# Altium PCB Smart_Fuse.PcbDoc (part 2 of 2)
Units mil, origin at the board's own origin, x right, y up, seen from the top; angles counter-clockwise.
Board outline 4000 x 2763 mil, 4 copper layers (Top Layer, Signal Layer 1, Signal Layer 2, Bottom Layer), stack 61.6 mil thick; 113 components, 65 nets, 281 pads, 450 vias.
Unrouted connection lines stored in the file: 2.
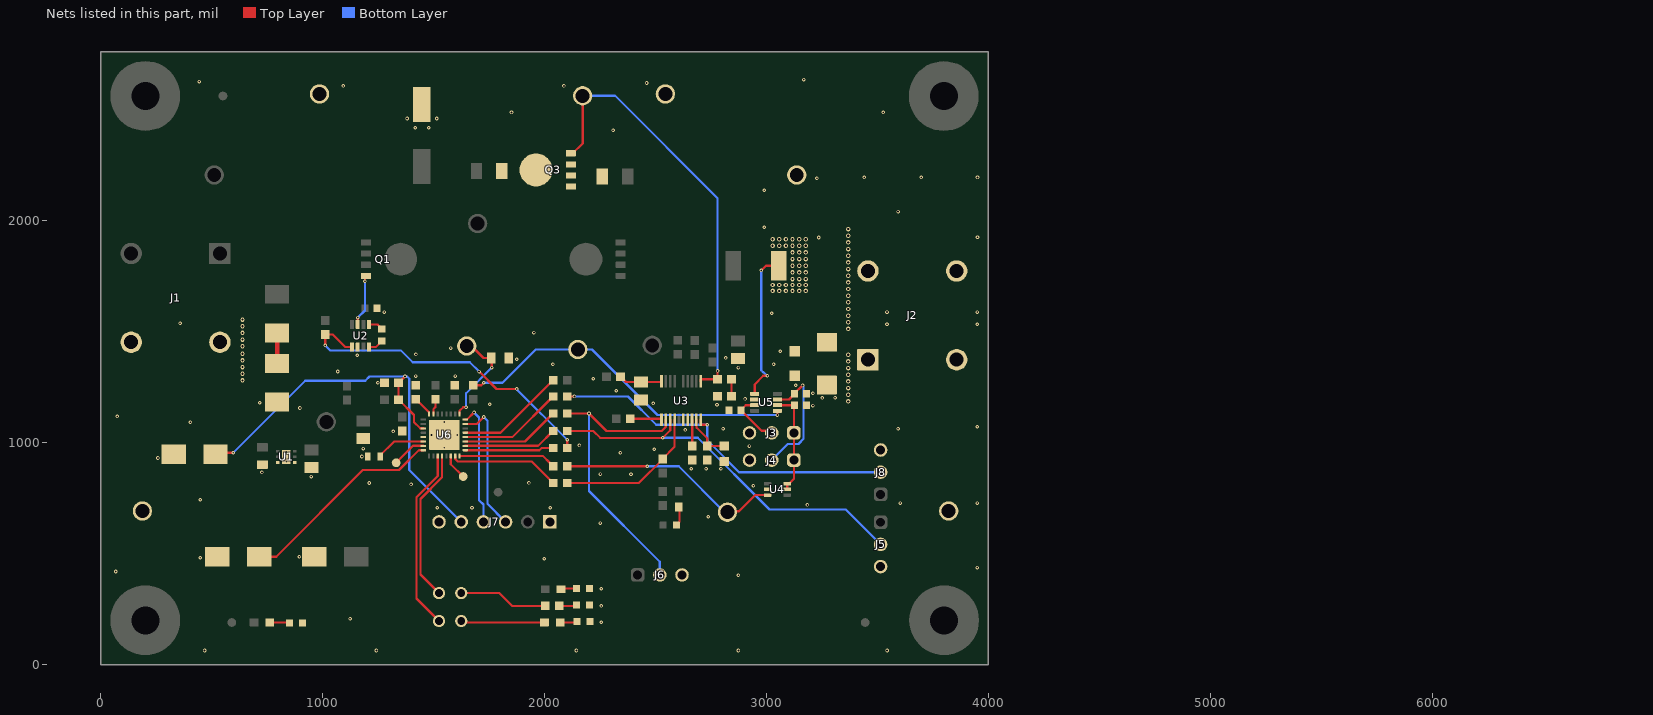
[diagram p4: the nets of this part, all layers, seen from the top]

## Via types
v1: diameter 20, hole 10, Top Layer to Bottom Layer, 262 vias
v2: diameter 16, hole 8, Top Layer to Bottom Layer, tented both sides, 179 vias
v3: diameter 19.68, hole 7.87, Top Layer to Bottom Layer, 7 vias
v4: diameter 34, hole 16, Top Layer to Bottom Layer, tented both sides, 2 vias

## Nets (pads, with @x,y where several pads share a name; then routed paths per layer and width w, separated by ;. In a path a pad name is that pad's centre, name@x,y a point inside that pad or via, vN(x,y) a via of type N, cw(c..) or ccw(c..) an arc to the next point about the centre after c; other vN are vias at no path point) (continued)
"Gate 2": Q3.4 R9.2 TP5.1 U3.11 | length 1994.7
  Top Layer w10: Q3.4@2118.01,2304.8 2126.87,2304.8 2171.12,2349.05 TP5.1@2171.12,2563.82 TP5.1@2171.12,2572.89 ; U3.11@2703.54,1277.07 2703.54,1285.37 2704.45,1286.28 R9.2@2779.16,1286.28 v2(2779.16,1323.83)
  Bottom Layer w10: TP5.1@2171.12,2563.82 2317.45,2563.82 2779.16,2102.11 v2(2779.16,1323.83)
GND: C1.1 C2.2 C3.2 C4.2 C5.2 C8.2 C9.2 C10.1 C11.2 C12.2 C13.2 C14.1 C15.1 C16.2 C17.2 C18.2 C19.1 D2.1 D3.2 D4.1 D6.2 D7.2 D8.2 D9.2 J1.2 J2.1 J3.3 J4.3 J5.3 J6.3 J7.1 J7.6 J8.3 R8.1 R10.2 R16.1 S1.1 S2.1 S3.1 TP9.1 TP10.1 TP11.1 TP12.1 U1.3 U1.4 U1.7@835.26,936.53 U2.2 U3.6 U3.7 U4.2 U5.2 U6.5 U6.33 | length 0.7
  Top Layer w10: U2.2@1157.34,1431.21 U2.2@1157.83,1430.72
  other v1: 3368,1186.73 3368,1216.73 3368,1246.73 3368,1276.73 637.98,1281.22 3368,1306.73 637.98,1311.22 3368,1336.73 637.98,1341.22 3368,1366.73 637.98,1371.22 3368,1396.73 637.98,1401.22 637.98,1435.31 637.98,1465.31 637.98,1495.31 637.98,1525.31 637.98,1555.31
  other v2: 467,64 1241.76,64 2143,64 2873,64 3543.31,64 2254.83,191.12 1122.76,207.16 2254.83,264.97 2254.83,341.99 2873,403 67,420 3950,437.57 1997.57,477.36 448,482 894.57,486.59 2250,638 2737,667 1516.16,707.59 1672.49,707.59 2025.51,707.59 3184.33,719.9 3602.36,728.35 3950,728.35 448,743.61 2940.61,806.54 1397.63,812.42 1209.38,818.83 1929.06,819 948.17,847.91 2389,858 2251,859 725.37,866.55 2660.5,883.24 2727.5,883.24 2794.5,883.24 257.01,931.56 1176.5,938.21 2341.57,955.59 2494,971 1182.26,973.72 2922.93,985 2156.46,988.33 1317.81,1051.07 2634,1058 2803.95,1062.99 3592.52,1062.99 3950,1071.92 403.54,1092.52 74,1119 896.82,1156.89 3208.8,1167.47 2776.66,1171.17 1752.81,1173.44 2488.81,1177.44 715.42,1180.52 2902.91,1197.5 3250.59,1202.13 3308.92,1202.67 3208.8,1222.9 2322.83,1234.17 3131.18,1259.63 1248.26,1270.56 2219.11,1288.56 1418.5,1300.48 1596.79,1300.48 1067.44,1321.36 2873,1339.09 2037.32,1354.09 3031.5,1354.35 1873.8,1376.73 2815.99,1382.53 1155.35,1394.56 1419.76,1398.52 1577.02,1426.93 1951.42,1496.8 3542.85,1533.76 3950,1533.76 357,1539 1276.59,1589.24 2308.34,2408.62 1416.7,2420.05 1477,2420.05 1380,2461.46 1513.7,2461.46 1850.39,2489.02 3526.16,2489.02 1092.52,2608.27 2086.61,2608.27 2459,2621.62 442.91,2627.95 3168,2637
  other v3: 835.26,914.88 835.26,958.19 1547.5,977.4 1489.43,1035.47 1547.5,1035.47 1605.57,1035.47 1547.5,1093.54
GPIO_EXTRA1: TP13.1 U6.7 | length 154.3
  Top Layer w10: TP13.1@1330.35,909.89 1406.71,986.25 U6.7@1453.01,986.25
GPIO_EXTRA2: TP14.1 U6.14 | length 115.9
  Top Layer w10: U6.14@1577.02,940.98 1577.02,903.43 TP14.1@1632.47,847.99
GPIO_FLT: R23.2 U6.21 | length 494.2
  Top Layer w10: U6.21@1641.99,1045.31 1801.1,1045.31 2037.32,1281.53 R23.2@2038.31,1281.53
GPIO_Ideal_Diode_EN: R19.2 U6.17 | length 400.7
  Top Layer w10: U6.17@1641.99,966.57 1975.99,966.57 1986.16,976.74 R19.2@2038.5,976.74
GPIO_INA_EN: R18.1 TP6.1 U4.3 | length 1058.6
  Top Layer w10: R18.1@2091.46,893.8 v2(2461.91,893.8) ; TP6.1@2823.5,687.29 2827.95,691.74 2876.14,691.74 2948.94,764.54 U4.3@3004.39,764.54
  Bottom Layer w10: v2(2461.91,893.8) 2603.8,893.8 2810.31,687.29 TP6.1@2851.62,687.29
GPIO_INA_EN_PIN: R18.2 U6.16 | length 442.2
  Top Layer w10: U6.16@1616.39,940.98 1991.33,940.98 2023.82,908.49 2023.82,907.51 2037.52,893.81 R18.2@2038.5,893.81
GPIO_INP: J5.2 R20.1 U3.3 | length 1720.9
  Top Layer w10: R20.1@2101.3,1053.17 2219.11,1053.17 2250.09,1022.19 2531.56,1022.19 v2(2531.72,1022.35) 2565.75,1056.37 2565.75,1102.03 2564.84,1102.93 U3.3@2565.75,1103.84
  Bottom Layer w10: v2(2531.72,1022.35) 2689.83,1022.35 3013.16,699.02 3356.98,699.02 J5.2@3514,542
GPIO_INP_PIN: R20.2 U6.18 | length 424
  Top Layer w10: U6.18@1641.99,986.25 1970.4,986.25 2037.32,1053.17 R20.2@2038.31,1053.17
GPIO_LPM: J6.2 R21.1 U3.2 | length 1376.8
  Top Layer w10: R21.1@2101.3,1131.92 v2(2199.83,1131.92) 2278.58,1053.17 2527.23,1053.17 2545.16,1071.1 2545.16,1102.93 U3.2@2546.06,1103.84
  Bottom Layer w10: v2(2199.83,1131.92) 2199.83,782.72 2518.87,463.67 J6.2@2518.87,404.3
GPIO_LPM_PIN: R21.2 U6.19 | length 448.5
  Top Layer w10: U6.19@1641.99,1005.94 1911.34,1005.94 2037.32,1131.92 R21.2@2038.31,1131.92
GPIO_SCP_TEST: R22.2 U6.20 | length 472.2
  Top Layer w10: U6.20@1641.99,1025.62 1854.18,1025.62 2037.32,1208.77 R22.2@2038.31,1208.77
GPIO_WAKE: R17.2 U6.15 | length 501.2
  Top Layer w10: U6.15@1596.71,940.98 1596.79,940.9 1596.79,926.8 1607.6,915.98 1941.35,915.98 2023.82,833.52 2023.82,832.53 2037.52,818.83 R17.2@2038.5,818.83
Ideal_Diode_EN: R1.1 R19.1 U2.1 | length 1497.1
  Top Layer w10: v2(1011.54,1438.92) R1.1@1011.54,1488.29 1045.3,1488.29 1102.39,1431.21 U2.1@1131.75,1431.21 ; v2(1704.49,1320.9) 1782.65,1242.75 v2(1873.8,1242.75) ; v2(2101.3,1013.56) 2101.3,976.94 R19.1@2101.5,976.74
  Bottom Layer w10: v2(1011.54,1438.92) 1035.02,1415.44 1353.02,1415.44 1405.22,1363.24 1662.15,1363.24 v2(1704.49,1320.9) ; v2(1873.8,1242.75) 1876.8,1239.75 1876.8,1238.05 v2(2101.3,1013.56)
Ideal_diode_Gate: Q1.4 U2.7 | length 237.9
  Top Layer w10: U2.7@1157.34,1533.57 1157.59,1533.82 1157.59,1564.23 v2(1157.83,1564.47) ; v2(1189.98,1728) 1189.98,1747.87 Q1.4@1194.37,1752.27 ; Q1.4@1191.67,1747.1 Q1.4@1194.37,1749.8
  Bottom Layer w10: v2(1157.83,1564.47) 1189.98,1596.63 v2(1189.98,1728)
INA_OUT: R24.1 TP7.1 U5.5 | length 1579.3
  Top Layer w10: R24.1@1678.09,1258.88 1713.63,1258.88 v2(1725.31,1270.56) ; U5.5@3048.68,1144.06 3049,1143.74 v2(3049,1125)
  Bottom Layer w10: v2(1725.31,1270.56) 1809.97,1270.56 1959.75,1420.34 TP7.1@2149.42,1420.34 2212.98,1420.34 2508.32,1125 v2(3049,1125)
INA_VS: C10.2 J3.1 J4.1 U4.5 U4.6 U5.6 | length 466.6
  Top Layer w10: U5.6@3048.68,1169.65 3114.53,1169.65 3123.13,1161.05 J3.1@3123.13,1044.67 J4.1@3123.13,922.28 3123.13,837.02 3104.7,818.59 3095.84,818.59 U4.6@3092.97,815.72 U4.5@3092.97,790.13
ISCP/LWU: R8.2 U3.8 | length 119.4
  Top Layer w10: R8.2@2664.82,983.78 U3.8@2664.82,1103.19
Low_Power_Drain: Q3.5 R4.1
Low_Power_Source: Q3.1 Q3.2 Q3.3 R11.2
LPM_ON_LED: J10.2 U6.12 | length 706
  Top Layer w10: J10.2@1537.4,309.07 1439.9,406.57 1439.9,746.62 1537.65,844.37 U6.12@1537.65,934.17
NetC7_2: C7.2 U2.4 | length 70
  Top Layer w10: U2.4@1208.52,1431.21 1239.24,1431.21 1254.9,1446.87 1254.9,1447.86 1265.65,1458.6 C7.2@1266.63,1458.6
NetC9_1: C9.1 R9.1 | length 76.5
  Top Layer w10: C9.1@2842.15,1209.78 R9.1@2842.15,1286.28
NetC11_1: C11.1 J4.2 U5.7 | length 566.4
  Top Layer w10: U5.7@3048.68,1195.24 3100.67,1195.24 3125.28,1219.85 C11.1@3125.28,1220.83 3125.28,1221.81 3161.93,1258.47 v2(3162.18,1258.47)
  Bottom Layer w10: J4.2@3023.13,922.28 3095.51,994.67 3143.42,994.67 3166.52,1017.76 3166.52,1252.5 3162.18,1256.84 v2(3162.18,1258.47) v2@3162.05,1258.47
NetC12_1: C12.1 J3.2 U5.3 | length 252.4
  Top Layer w10: U5.3@2946.31,1169.65 2906.1,1169.65 2885.01,1148.55 2885.01,1146.59 2977.62,1053.97 3013.82,1053.97 J3.2@3023.13,1044.67
NetD1_2: D1.2 D2.2 | length 137.7
  Top Layer w20: D2.2@793.92,1357.57 D1.2@793.92,1495.3
NetD5_2: D5.2 R30.2 | length 97.4
  Top Layer w10: D5.2@2593.22,628.5 2608.05,643.81 R30.2@2608.05,719.9
NetD6_1: D6.1 R26.1 | length 65.8
  Top Layer w10: R26.1@2069.81,190.23 D6.1@2135.56,190.23
NetD7_1: D7.1 R27.1 | length 70.9
  Top Layer w10: R27.1@2065.87,264.97 D7.1@2136.74,264.97
NetD8_1: D8.1 R28.1 | length 70.5
  Top Layer w10: R28.1@2073.74,340.21 2076.69,343.17 D8.1@2143,343.17
NetD9_1: D9.1 R29.1 | length 89.4
  Top Layer w10: R29.1@760.81,190.23 846.07,190.23 D9.1@849.03,187.28
NetJ9_1: J9.1 R26.2 | length 377.8
  Top Layer w10: J9.1@1623.8,196.76 1630.34,190.23 R26.2@1998.94,190.23
NetJ10_1: J10.1 R27.2 | length 411.9
  Top Layer w10: J10.1@1614.83,322.67 J10.1@1623.8,322.67 1795.31,322.67 1853.01,264.97 R27.2@2002.88,264.97
NetR25_2: R25.2 U6.31 | length 70
  Top Layer w10: U6.31@1498.28,1129.95 1498.36,1130.03 1498.36,1151.44 1508.13,1161.2 R25.2@1508.13,1195.89
NRST: C17.1 J7.5 R15.1 S1.2 U6.3 | length 2061.7
  Top Layer w10: S1.2@522.78,947.88 529.97,955.07 v2(596.29,955.07) ; v2(1370.46,1299.26) 1341.76,1270.56 C17.1@1340.78,1270.56 R15.1@1340.78,1193.89 1341.76,1193.89 1410.67,1124.98 1410.67,1093.23 1438.83,1065.07 1452.93,1065.07 U6.3@1453.01,1064.99
  Bottom Layer w10: v2(596.29,955.07) 921.24,1280.02 1191.65,1280.02 1210.89,1299.26 v2(1370.46,1299.26) 1371.61,1298.11 1380.73,1298.11 1389.96,1288.89 1389.96,877.36 J7.5@1623.8,643.52
Output: D3.1 D4.2 J2.2 R14.1 TP8.1 U5.1 | length 690.4
  Top Layer w10: U5.1@2946.31,1220.83 2946.31,1262.64 2985.51,1301.84 v2(3003.68,1301.84) ; v2(2976.25,1776.89) 2997.1,1797.74 R14.1@3055.15,1797.74
  Bottom Layer w10: v2(2976.25,1776.89) 2976.25,1756.89 2976.25,1327.43 2986.56,1317.13 2986.76,1317.13 3002.05,1301.84 v2(3003.68,1301.84)
  other v1: 3368,1513 3368,1543 3368,1573 3368,1603 3368,1633 3368,1663 3026.93,1684.69 3056.93,1684.69 3086.93,1684.69 3116.94,1684.69 3146.94,1684.69 3176.94,1684.69 3368,1693 3026.93,1711.25 3056.93,1711.25 3086.93,1711.25 3116.94,1711.25 3146.94,1711.25 3176.94,1711.25 3368,1723 3116.94,1737.82 3146.94,1737.82 3176.94,1737.82 3368,1753 3116.94,1767.82 3146.94,1767.82 3176.94,1767.82 3368,1783 3116.94,1797.82 3146.94,1797.82 3176.94,1797.82 3368,1813 3116.94,1827.82 3146.94,1827.82 3176.94,1827.82 3368,1843 3116.94,1857.82 3146.94,1857.82 3176.94,1857.82 3368,1873 3026.93,1887.82 3056.93,1887.82 3086.93,1887.82 3116.94,1887.82 3146.94,1887.82 3176.94,1887.82 3368,1903 3026.93,1917.82 3056.93,1917.82 3086.93,1917.82 3116.94,1917.82 3146.94,1917.82 3176.94,1917.82 3368,1933 3368,1963
  other v2: 3061.18,1413 3023.13,1584 3542.85,1589 3950,1589 3235.33,1925.16 3950.53,1926 2990,1971 3592.52,2041.96 2990,2138.11 3226.8,2191.79 3440,2196 3697,2196 3950.53,2196
OUTPUT_ON_LED: J9.2 U6.11 | length 845.1
  Top Layer w10: U6.11@1517.97,940.98 1517.97,849.96 1422.03,754.02 1422.03,298.54 J9.2@1537.22,183.34
ROSC: R16.2 U6.6 | length 224.6
  Top Layer w10: R16.2@1259.17,938.51 1259.17,943.43 1321.68,1005.94 U6.6@1453.01,1005.94
SCP_TEST: J8.2 R22.1 U3.10 | length 1646.7
  Top Layer w10: R22.1@2101.3,1208.77 v2(2134.09,1208.77) ; U3.10@2703.54,1103.84 2703.54,1082.17 2704.45,1081.27 v2(2732.84,1081.27)
  Bottom Layer w10: v2(2134.09,1208.77) 2375.17,1208.77 2502.67,1081.27 v2(2732.84,1081.27) 2732.84,1010.83 2876.18,867.49 J8.2@3514,867.49
STATE_TOGGLE_SW: S3.2 U6.8 | length 937.6
  Top Layer w10: S3.2@714.19,486.59 789.86,486.59 1180.61,877.33 1343.83,877.33 1433.07,966.57 U6.8@1453.01,966.57
SWCLK: J7.4 U6.24 | length 563.7
  Top Layer w10: U6.24@1641.99,1104.36 1648.72,1104.36 1681.04,1136.69 v2(1681.67,1136.69)
  Bottom Layer w10: v2(1681.67,1136.69) 1704.44,1113.92 1704.44,741.43 1723.8,722.06 J7.4@1723.8,643.52
SWDIO: J7.3 U6.23 | length 609.8
  Top Layer w10: U6.23@1641.99,1084.68 1693.83,1084.68 v2(1725.31,1116.17)
  Bottom Layer w10: v2(1725.31,1116.17) 1742,1099.48 1742,725.32 J7.3@1823.8,643.52
TMR: C8.1 R10.1 U3.9 | length 207.7
  Top Layer w10: U3.9@2683.86,1103.84 2684.76,1102.93 2684.76,1068.04 2732.84,1019.96 C8.1@2732.84,985.28 R10.1@2801.74,985.28
TPS1213_EN: R5.2 U3.1 | length 145.4
  Top Layer w10: R5.2@2385.03,1108.47 2525.47,1108.47 2526.38,1107.56 U3.1@2526.38,1103.84
TPS1213_VS: C5.1 R2.2 U3.20 | length 197.5
  Top Layer w10: R2.2@2341.57,1297.76 2342.56,1297.76 2366.56,1273.76 C5.1@2433.37,1273.76 2525.47,1273.76 2526.38,1274.67 U3.20@2526.38,1277.07
VCAP: C7.1 U2.5 | length 70.7
  Top Layer w10: U2.5@1208.52,1533.57 1246.79,1533.57 1254.9,1525.45 1254.9,1524.47 1267.61,1511.76 C7.1@1269.6,1511.76
VCORE: C16.1 U6.32 | length 93.2
  Top Layer w10: C16.1@1418.5,1197.7 1418.5,1196.71 1432.2,1183.01 1433.19,1183.01 1478.6,1137.6 U6.32@1478.6,1129.95
VREF-: C19.2 TP16.1 U6.25 | length 454.4
  Top Layer w10: U6.25@1616.39,1129.95 1616.39,1144.39 1632.47,1160.47 v2(1645.92,1160.47) ; TP16.1@1648.72,1436.35 1669.55,1436.35 1690.11,1415.8 1690.9,1415.8 1724.5,1382.2 C19.2@1759.56,1382.2 1761.56,1380.2 v2(1761.56,1338.86)
  Bottom Layer w10: v2(1645.92,1160.47) 1645.92,1223.23 v2(1761.56,1338.86)
WAKE: R13.1 R17.1 U3.4 | length 684.6
  Top Layer w10: R17.1@2091.45,818.83 2424.24,818.83 2531.62,926.21 R13.1@2531.62,927.2 2531.62,928.18 2585.43,982 U3.4@2585.43,1103.84
pads on no net: FID1.1 FID2.1 FID3.1 H1.1 H2.1 H3.1 H4.1 H5.0 H6.0 H7.0 H8.0 LBL1.0 U1.5 U1.7@835.26,918.82 U1.7@835.26,954.25 U3.19 U4.4 U5.4 U6.1 U6.2 U6.27 U6.28 U6.29 U6.30

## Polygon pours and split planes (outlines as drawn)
Output on Top Layer "TOP_LAYER_OUTPUT_P071" (solid, remove dead copper, pour order 71): 3965.42,1559.13 3974.51,1568.22 3974.51,2357.38 3944.43,2387.46 2990.98,2387.46 2960.02,2356.49 2960.02,1923.27 3020.01,1863.27 3020.01,1732.3 2960.02,1672.3 2960.02,1415.13 2972.02,1403.13 2990.02,1385.13 3309.02,1385.13 3483.02,1559.13
FETS_SOURCE on Top Layer "TOP_LAYER_FETS_SOURCE_P070" (solid, remove dead copper, pour order 70): 2311.36,1520.47 2308.46,1523.37 2308.46,1526.28 2308.54,1533.56 2308.34,1533.76 2308.34,2357.87 2340.79,2390.31 2926.19,2390.31 2946,2370.51 2946,1923.3 2885.66,1862.96 2885.66,1732.62 2946,1672.28 2946,1430.78 2935.22,1420 2832,1420 2815,1403 2722,1403 2722,1404 2713,1413 2713,1428 2739,1454 2773,1454 2779,1460 2779,1521.25 2773.25,1527 2320.79,1527 2314.26,1520.47
"3V3 LDO" on Top Layer "TOP_LAYER_3V3_LDO_P067" (solid, remove dead copper, pour order 67): 905.51,1072.83 1053.15,1220.47 1299.84,1220.47 1311.31,1209 1311.31,1167.59 1327.95,1150.95 1369.18,1150.95 1388.21,1131.92 1388.21,1089.89 1383,1084.68 1264.02,1084.68 1241.76,1062.42 1118.54,1062.42 997.09,940.98 912.42,940.98 905.51,947.88
"Gate 1" on Top Layer "TOP_LAYER_GATE_1_P073" (solid, remove dead copper, pour order 73): 2584.7,1489.47 2576.7,1481.47 2576.7,1439.47 2581.7,1434.47 2693.16,1434.47 2699.3,1440.61 2699.3,1479.87 2689.7,1489.47
Low_Power_Drain on Top Layer "TOP_LAYER_LOW_POWER_DRAIN_P065" (solid, remove dead copper, pour order 65): 1790.42,2390.31 1768.91,2368.8 1768.91,2149.66 1789.76,2128.81 2064.45,2128.81 2077.83,2142.2 2077.83,2356.89 2044.41,2390.31
FETS_DRAIN on Top Layer "TOP_LAYER_FETS_DRAIN_P048" (solid, remove dead copper, pour order 69): 2287.73,1525.69 2294.03,1519.39 2299.19,1519.39 2299.19,1531.01 2299.19,2106 2286.57,2118.62 1786.63,2118.62 1759.49,2145.76 1759.49,2367.95 1739.2,2390.31 1270.95,2390.31 1246,2365.36 1246,1694.32 1323.28,1617.04 1388.2,1617.04 1478.24,1527 2273.95,1527 2276.36,1525.69
Low_Power_Source on Top Layer "TOP_LAYER_LOW_POWER_SOURCE_P064" (solid, pour order 64): 2088.94,2264.92 2100.77,2276.75 2272.29,2276.75 2287.44,2261.6 2287.44,2153.81 2286.91,2146.7 2277.91,2137.7 2096.02,2137.7 2088.94,2144.78
Batt_In on Top Layer "TOP_LAYER_BATT_IN_P068" (solid, remove dead copper, pour order 68): 1161.8,1671.17 1169.73,1663.25 1198.5,1663.25 1204.78,1656.97 1204.78,1589.95 1125.21,1589.95 1062.26,1527 960.82,1527 903.82,1584 23,1584 -1,1608 -1,2390.31 1207.44,2390.31 1231,2366.75 1231,1799.88 1231,1781.11 1227.09,1777.2 1167.43,1777.2 1161.8,1771.57
GND on Top Layer "TOP_LAYER_GND_P082" (solid, remove dead copper, pour order 82): 0,2763 0,0 4000,0 4000,2763
GND on Signal Layer 2 "SIGNAL_LAYER_2_GND_P083" (solid, remove dead copper, pour order 83): 0,2763 0,0 4000,0 4000,2763
Batt_In on Signal Layer 2 "SIGNAL_LAYER_2_BATT_IN_P076" (solid, remove dead copper, pour order 76): 1173.13,1642.71 1211.32,1642.71 1231,1662.4 1231,1747 1231,2366.75 1207.44,2390.31 -1,2390.31 -1,1608 23,1584 903.82,1584 960.82,1527 1057.42,1527
FETS_SOURCE on Signal Layer 2 "SIGNAL_LAYER_2_FETS_SOURCE_P080" (solid, remove dead copper, pour order 80): 2308.34,2357.3 2341.36,2390.31 2911.77,2390.31 2946,2356.09 2946,1923.3 2885.66,1862.96 2885.66,1732.7 2946,1672.35 2946,1430.78 2935.22,1420 2832,1420 2815,1403 2643.51,1403 2532.57,1522.23 2340.41,1522.23 2308.34,1554.3 2308.34,1763.25
FETS_DRAIN on Signal Layer 2 "SIGNAL_LAYER_2_FETS_DRAIN_P078" (solid, remove dead copper, pour order 78): 2274.55,1527 2300,1552.45 2300,2355.28 2264.97,2390.31 1270.95,2390.31 1246,2365.36 1246,1694.32 1323.28,1617.04 1388.2,1617.04 1478.24,1527
"3V3 LDO" on Signal Layer 2 "SIGNAL_LAYER_2_3V3_LDO_P072" (solid, remove dead copper, pour order 72): 1265.87,1072.11 1271.25,1084.67 1277.96,1084.67 1278.43,1084.67 1379.99,1084.67 1388.21,1092.89 1388.21,1128.93 1366.19,1150.95 1327.95,1150.95 1311.31,1167.59 1311.31,1209.01 1299.84,1220.48 1053.15,1220.48 905.52,1072.84 905.52,944.89 909.42,940.98 996.98,940.98 1118.42,1062.42 1256.18,1062.42
Output on Signal Layer 2 "SIGNAL_LAYER_2_OUTPUT_P081" (solid, remove dead copper, pour order 81): 3965.42,1559.13 3974.51,1568.22 3974.51,2357.38 3941.58,2390.31 2993.84,2390.31 2960,2356.47 2960,1923.32 3019.7,1863.64 3019.7,1732.11 2960,1672.41 2960,1415.15 2990.02,1385.13 3308.99,1385.13 3482.99,1559.13
"3V3 LDO" on Signal Layer 2 "SIGNAL_LAYER_2_3V3_LDO_P074" (solid, remove dead copper, pour order 74): 993.14,1160.47 964.57,1131.89 964.57,1072.83 974.41,1062.99 1089.14,1062.99 1122.05,1095.9 1122.05,1130.94 1092.52,1160.47
FETS_DRAIN on Bottom Layer "BOTTOM_LAYER_FETS_DRAIN_P079" (solid, remove dead copper, pour order 79): 2299.19,1625 2299.47,1625.28 2299.47,1717.82 2299.19,1717.82 2299.19,2364.19 2273.07,2390.31 1270.95,2390.31 1246,2365.36 1246,1694.32 1323.28,1617.04 1388.2,1617.04 1478.24,1527 2273.95,1527 2299.19,1552.24
GND on Bottom Layer "BOTTOM_LAYER_GND_P085" (solid, remove dead copper, pour order 85): 0,2763 0,0 4000,0 4000,2763
Output on Bottom Layer "BOTTOM_LAYER_OUTPUT_P084" (solid, remove dead copper, pour order 84): 2985.05,1390.95 2985.05,1697.57 3020.01,1732.53 3020.01,1863.27 2960.02,1923.27 2960.02,2356.49 2990.98,2387.46 3944.43,2387.46 3974.51,2357.38 3974.51,1568.22 3965.42,1559.13 3483.02,1559.13 3309.02,1385.13 2990.87,1385.13
Batt_In on Bottom Layer "BOTTOM_LAYER_BATT_IN_P077" (solid, remove dead copper, pour order 77): 1173.13,1637.15 1173.13,1732.62 1231,1790.5 1231,2366.75 1208.75,2389 -1,2389 -1,1608 23,1584 903.82,1584 960.32,1527.5 1063.48,1527.5
GND on Signal Layer 1 "SIGNAL_LAYER_1_GND_P075" (solid, remove dead copper, pour order 75): -2.23,2763 3997.37,2763 3997.37,0 -2.23,0

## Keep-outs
Keep-Out Layer:
  text ".Layer_Name" at 577,-858.49 h60

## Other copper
Top Layer:
  pour cut-out: 1631.79,1229.08 1652.38,1249.67 1664.29,1237.77 1664.29,1196.59 1603.93,1196.59 1537.48,1196.59 1533.16,1200.9 1533.16,1204.88 1540.2,1211.92 1540.2,1229.08
  pour cut-out: 3137.63,1246.79 3056.93,1246.79 3056.93,1125.37 3137.63,1125.37
  pour cut-out: 787.82,186.37 808.74,209 707.55,209.4 684.27,186.12 665.79,169.12 667.29,167.62 787.82,167.62
  pour cut-out: 2168.74,353.8 1732.52,355.52 1518.9,159 2168.74,159
  pour cut-out: 2729.33,1063.27 2775.42,1017.18 2794.17,1017.18 2814.85,996.5 2814.85,955 2649,955 2644,960 2644,1033 2652,1033 2669,1050 2710,1050 2723.27,1063.27
  pour cut-out: 2131.02,1015.25 2151.95,1037.88 2050.76,1038.28 2027.48,1015 2009,998 2010.5,996.5 2131.02,996.5
  pour cut-out: 1707.08,1173.44 1707.08,1211.89 1722.92,1227.73 1777.68,1227.73 1760.72,1244.69 1706.79,1244.69 1657.53,1195.42 1657.53,1174.32 1813.72,1044.9 1813.72,1066.8 1819.65,1072.73 1819.65,1084.68 1817.96,1082.99 1797.53,1082.99
  pour cut-out: 1310.78,1240.91 1303.74,1233.87 1303.74,1229.89 1308.06,1225.58 1374.51,1225.58 1378.41,1216.98 1412.02,1216.98 1370.92,1258.07 1310.78,1258.07
  pour cut-out: 1113.76,1514.38 1227.61,1514.38 1227.61,1449.93 1113.86,1450.92
  pour cut-out: 1202.97,1585.86 1210.7,1585.86 1265.48,1539.47 1202.97,1539.47
  pour cut-out: 1206.97,1647.86 1277.42,1647.86 1294.06,1631.22 1318.51,1606.76 1274.61,1606.76 1266.79,1623.95 1224.96,1623.95 1207.14,1606.13
  pour cut-out: 3027,1289.97 2967.29,1289.97 2967.29,1126 3027,1126
  pour cut-out: 3020.89,834.13 3021.65,834.89 3080.39,834.89 3080.39,746.8 3020.71,746.8
  pour cut-out: 2900,1409.8 2953.8,1409.8 2960,1416 2956,1420 2900,1420
  pour cut-out: 2515.78,973.15 2592.38,1061.88 2602.62,1061.88 2611,631 2616,626 2604,614 2543,614 2543,691.28 2432,802.28 2432,867.48 2423.02,878.5 2428.94,884.42
  pour cut-out: 1278.43,910.75 1300.18,889 1354,889 1362,881 1435,954 1436,954 1436,979 1278.43,979
  pour cut-out: 1624.02,905.51 1624.02,944.88 1968.5,944.88 1998.03,974.41 1998.44,974 2133,974 2133,845 2129.98,791.57 2043.87,800.13 1938,906 1681,906
  pour cut-out: 2510.24,1259.84 2510.24,1123.76 2718.59,1123.76 2719.68,1124.85 2719.68,1259.84
  text ".Layer_Name" at 577,-858.49 h60
Signal Layer 2:
  pour cut-out: 2900,1409.8 2953.8,1409.8 2960,1416 2956,1420 2900,1420
  pour cut-out: 1268.58,1614.38 1322.19,1614.38 1331.09,1606.85 1268.58,1606.85
Bottom Layer:
  pour cut-out: 2724.17,1095.4 2724.17,1095.12 2748.13,1071.16 2772.37,1095.4 2945.74,1095.4 2946.9,1096.56 2957.16,1109.71 2936.71,1125 2576.62,1125 2561.4,1137 2465,1137 2465.29,1133.11 2465.29,1132.71 2502.6,1095.4
  pour cut-out: 2954.81,1914.5 2946,1923.3 2885.66,1862.96 2885.66,1732.7 2927.97,1690.38 2930.75,1423.82 2985.38,1384.42 2985.38,1883.92
  pour cut-out: 1805.38,629.6 1792.79,617.01 1726.83,617.01 1719.86,623.99 1719.86,667.04 1805.38,666.96
  pour cut-out: 1789.24,821.49 1756.8,789.05 1723.8,789.05 1703.71,809.14 1703.71,868.97 1789.24,868.89
  pour cut-out: 1434.53,1321.36 1455.86,1347.95 1438.35,1370.72 1340.35,1370.72 1340.35,1353.55 1333.31,1346.51 1333.31,1342.53 1337.63,1338.22 1404.08,1338.22 1411.74,1321.36
  pour cut-out: 2622,994.34 2639.5,1011.84 2639.5,1014.8 2630.75,1014.8 2622,1006.06 2524.01,1006.06 2620.96,925.55 2622,926.59
  pour cut-out: 3164.14,891.61 3173.13,882.61 3162.18,882.61 3083.06,994.67 3164.14,994.67
  pour cut-out: 2724.17,1066.15 2724.17,1037.64 2572.11,1037.64 2572.11,1055.2 2582.89,1065.97
  pour cut-out: 2227.03,1164.01 2227.03,1185.56 2219.11,1193.47 2219.14,1193.51 2263.78,1193.51
  text ".Layer_Name" at 577,-858.49 h60

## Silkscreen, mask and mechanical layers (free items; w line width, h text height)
Top Overlay:
  text "GND" at 928.2,2445.97 h60
  text "GATE 2" at 2078.49,2437.48 h60
  text "GND" at 2487.22,2437.48 h60
  text "BATTERY IN" at 629,2182 h60
  text "OUTPUT" at 3041.93,2072.25 h60
  text "FETS DRAIN" at 1549.94,1866.81 h60
  text "+" at 769.85,1801.78 h200
  text "+" at 3225.13,1801.78 h200
  text "GATE 1" at 2374.33,1520.46 h60
  text "INA OUT" at 1999.98,1508.67 h60
  text "VREF-" at 1402.28,1415.7 h60
  text "3V3" at 967.55,1178.1 h60
  text "GND" at 3173.65,981.52 h40
  text "VREF2" at 3259.19,981.52 h40
  text "3V3" at 3388.12,981.96 h40
  text "GND" at 3577.89,969.47 h60
  text "SCP_TEST" at 3577.89,875.23 h60
  text "3V3" at 3388.12,859.58 h40
  text "GND" at 3173.65,859.13 h40
  text "VREF1" at 3259.19,859.13 h40
  text "MCU RESET" at 274.23,819.5 h60
  text "3V3" at 3577.89,766.2 h60
  text "BSL INVOKE" at 1558.29,735.86 h40
  text "3V3" at 3577.89,625.15 h60
  text "GND" at 1506.57,573.79 h60 r270
  text "NRST" at 1607.44,573.79 h60 r270
  text "SWCLK" at 1708.31,573.79 h60 r270
  text "SWDIO" at 1809.18,573.79 h60 r270
  text "3V3" at 1910.05,573.79 h60 r270
  text "GND" at 2010.42,573.79 h60 r270
  text "GND" at 125,550.34 h60
  text "GND" at 3760.67,550.34 h60
  text "INP" at 3577.89,521.81 h60
  text "INA EN" at 2732.84,502.58 h60
  text "GND" at 3577.89,422.5 h60
  text "Toggle Power Mode" at 421.99,361.54 h50
  text "Toggle Fuse Channel" at 855.69,351.56 h50
  text "3V3" at 2397.43,328.32 h60 r270
  text "LPM" at 2504.93,328.32 h60 r270
  text "GND" at 2593.45,328.32 h60 r270
  text "Use S2 or S3 to Clear Latch" at 521.27,293.17 h50
  text ".PRJ_Number" at 2737,116 h108.27
  text ".Layer_Name" at 577,-858.49 h60
Bottom Overlay:
  text ".Layer_Name" at 577,-858.49 h60
Top Paste:
  text ".Layer_Name" at 577,-858.49 h60
Bottom Paste:
  text ".Layer_Name" at 577,-858.49 h60
Top Solder:
  text ".Layer_Name" at 577,-858.49 h60
  text ".Layer_Name" at 577,-858.49 h60
Bottom Solder:
  text ".Layer_Name" at 577,-858.49 h60
Drill Guide:
  text ".Layer_Name" at 577,-858.49 h60
M1 Board Outline:
  the board outline again, w10
  text ".Layer_Name" at 577,-858.49 h60
M2 Board Dimensions:
  rectangle: 0,-275 125,-150
  rectangle: 125,-400 500,-275
  lines w7: 0,-275 1000,-275 ; 125,-400 125,-150 ; 250,-400 250,-150 ; 500,-400 500,-150 ; 750,-400 750,-150 ; 0,-400 1000,-400 1000,-150 0,-150 0,-400
  text ".Layer_Name" at 577,-858.49 h60
M3 3D STEP Top:
  text ".Layer_Name" at 577,-858.49 h60
M4 3D STEP Bottom:
  text ".Layer_Name" at 577,-858.49 h60
Top M5 Assembly Top/M6 Assembly Bottom:
  lines w10: -292,-930.17 6308,-930.17 ; -292,-726.83 6310,-726.83 ; -292,-523.5 -292,-1133.5 3713,-1133.5 6310,-1133.5 6310,-523.5 -291.5,-523.5 -291.5,-1133.5 1284,-1133.5 ; 2173,-1133.5 2173,-523.5 ; 3440,-726.83 3440,-523.5 ; 4280,-726.83 4280,-523.5 ; 4902,-1140 4902,-937.17
  text "COMPONENTS MARKED 'DNP' SHOULD NOT BE POPULATED." at 1153.5,-318.5 h60
  text "ASSEMBLY VARIANT:" at 1153,-434 h60
  text ".VariantName" at 2189,-434 h60
  text "PCB VIEWED FROM TOP SIDE" at -228.5,-655.67 h60
  text "BOARD #:" at 2248,-655.67 h60
  text ".PRJ_Number" at 2793.5,-655.67 h60
  text "REV:" at 3638,-655.67 h60
  text ".PCB_Rev" at 3929.5,-655.67 h60
  text "SVN REV:" at 4476,-655.67 h60
  text ".VersionControl_RevNumber" at 4982,-655.67 h60
  text "TID #:" at 2248,-859 h60
  text ".TID" at 2793.5,-859 h60
  text "PLOT NAME =" at -228.5,-1064.34 h60
  text ".plot_File_Name" at 577,-1064.34 h60
  text "GENERATED    :" at 2250,-1064.34 h60
  text ".Print_Date" at 3119.5,-1064.34 h60
  text ".Print_Time" at 3848.5,-1064.34 h60
  text "TEXAS INSTRUMENTS" at 5113,-1064.34 h60
Bottom M5 Assembly Top/M6 Assembly Bottom:
  lines w10: -292.5,-727.33 6309.5,-727.33 ; -290.5,-930.67 6309.5,-930.67 ; 1115.5,-1140.5 1115.5,-937.67 ; 1737.5,-727.33 1737.5,-524 ; 2577.5,-727.33 2577.5,-524 ; 3844.5,-1134 3844.5,-524 ; 4733.5,-1134 6309,-1134 6309,-524 -292.5,-524 -292.5,-1134 2304.5,-1134 6309.5,-1134 6309.5,-524
  text "COMPONENTS MARKED 'DNP' SHOULD NOT BE POPULATED." at 6102,-318 h60
  text ".VariantName" at 5058,-434 h60
  text "ASSEMBLY VARIANT:" at 6097,-434 h60
  text ".VersionControl_RevNumber" at 1035.5,-656.17 h60
  text "SVN REV:" at 1541.5,-656.17 h60
  text ".PCB_Rev" at 2088,-656.17 h60
  text "REV:" at 2379.5,-656.17 h60
  text ".PRJ_Number" at 3224,-656.17 h60
  text "BOARD #:" at 3769.5,-656.17 h60
  text "PCB VIEWED FROM BOTTOM SIDE" at 6246,-656.17 h60
  text ".TID" at 3224,-859.5 h60
  text "TID #:" at 3769.5,-859.5 h60
  text "TEXAS INSTRUMENTS" at 904.5,-1064.84 h60
  text ".Print_Time" at 2169,-1064.84 h60
  text ".Print_Date" at 2898,-1064.84 h60
  text "GENERATED    :" at 3767.5,-1064.84 h60
  text ".plot_File_Name" at 5440.5,-1064.84 h60
  text "PLOT NAME =" at 6246,-1064.84 h60
M9 Title Sheet:
  drawing of 57 lines, arcs and shapes, not listed
  text "1" at 739.84,8036.5 h70
  text "2" at 3235.5,8036.5 h70
  text "3" at 5724.84,8036.5 h70
  text "4" at 8231.51,8036.5 h70
  text "5" at 10730.5,8036.5 h70
  text "6" at 13235.5,8036.5 h70
  text "A" at -416.5,6893.5 h70
  text "A" at 14383.5,6893.5 h70
  text "B" at -416.5,4513.5 h70
  text "B" at 14383.5,4513.5 h70
  text "C" at -416.5,2138.5 h70
  text "C" at 14383.5,2138.5 h70
  text "PROJECT TITLE:" at 11343.5,277.5 h45
  text ".PRJ_Title" at 11393.5,144.17 h70
  text "DESIGNED FOR:" at 11343.5,-23.5 h45
  text ".PRJ_Customer" at 11393.5,-163.5 h70
  text "D" at -416.5,-231.5 h70
  text "D" at 14383.5,-231.5 h70
  text "FILE NAME:" at 11343.5,-323.5 h45
  text ".PCB_File_Name_No_Path" at 11393.5,-443.5 h70
  text "Texas Instruments (TI) and/or its licensors do not warrant the accuracy or completeness of this specification" at 6374,-605.34 h45
  text "ENGINEER:" at 11343.5,-613.5 h45
  text "LAYOUT BY:" at 12848.5,-613.5 h45
  text "or any information contained therein. TI and/or its licensors do not warrant that this design will meet" at 6329.01,-718 h45
  text ".PRJ_Engineer" at 11393.5,-768.49 h70
  text ".PCB_Layout" at 12899,-768.49 h70
  text "the specifications, will be suitable for your application or fit for any particular purpose, or will operate in" at 6329.01,-830.67 h45
  text ".Layer_Name" at 577,-858.49 h60
  text "ALTIUM DESIGNER VERSION:" at 12848.5,-923.5 h45
  text "an implementation. TI and/or its licensors do not warrant that the design is production worthy. You should" at 6329.01,-943.33 h45
  text "completely validate and test your design implementation to confirm the system functionality for your application." at 6374,-1056 h45
  text ".print_Scale" at 11393.5,-1056.83 h70
  text ".Application_BuildNumber" at 12899,-1056.83 h70
  text "1" at 739.84,-1263.5 h70
  text "2" at 3235.5,-1263.5 h70
  text "3" at 5724.84,-1263.5 h70
  text "4" at 8231.51,-1263.5 h70
  text "5" at 10730.5,-1263.5 h70
  text "6" at 13235.5,-1263.5 h70
M10 Fab Notes:
  drawing of 189 lines, arcs and shapes, not listed
  text "DESIGN INFORMATION" at 12382.02,6356.17 h60
  text "MIN. TRACK WIDTH:" at 11737.46,6224.05 h60
  text "8" at 12833.7,6224.05 h60
  text "MIL" at 12988.46,6224.05 h60
  text "7.874" at 12667.32,6102.36 h60
  text "MIN. CLEARANCE:" at 11737.46,6099.92 h60
  text "MIL" at 12988.46,6099.92 h60
  text "MIN. VIA PAD SIZE:" at 11737.46,5975.8 h60
  text "16" at 12803.71,5975.8 h60
  text "MIL" at 12988.46,5975.8 h60
  text "0.05mm (2MIL)" at 12432.46,5845.9 h60
  text "MINIMUM ANNULAR RING" at 11408.23,5837.67 h60
  text "EXTERNAL" at 13140.46,5837.67 h60
  text "PER" at 11608.23,5727.55 h60
  text "IPC-D-275 CLASS 2 LEVEL C" at 11828.23,5727.54 h60
  text "MIL, HOLES" at 13316.46,5627.07 h60
  text "+/-" at 12924,5618.48 h60
  text "+/-" at 13778,5618.48 h60
  text "REGISTRATION TOLERANCES:" at 11408.23,5617.42 h60
  text "METAL" at 12608,5617.42 h60
  text "5" at 13184.2,5617.42 h60
  text "3" at 14017.2,5617.42 h60
  text "MIL" at 14133.46,5617.42 h60
  text "HOLE SIZE TOLERANCE (UNLESS OTHERWISE SPECIFIED):" at 11408.23,5519.1 h60
  text "+/-" at 13778,5516.23 h60
  text "3" at 14017.2,5515.17 h60
  text "MIL" at 14133.46,5515.17 h60
  text "MATERIAL:" at 11333.46,5377.52 h60
  text "FR-4 High Tg" at 12319.9,5249 h60
  text "X" at 12175.46,5241.01 h60
  text "FR-4" at 11754.46,5236.49 h60
  text "OTHER" at 13242.46,5236.49 h60
  text "62 MIL (1.6mm) +/-10%" at 12074.56,5093.46 h60
  text "X" at 11954.46,5091.01 h60
  text "THICKNESS:" at 11408.23,5085.24 h60
  text "OTHER" at 13359.46,5085.24 h60
  text "TOLERANCE:" at 11408.23,4946.92 h60
  text "X" at 12256.46,4946.92 h60
  text "ANSI IPC-6012 TYPE 3 CLASS 2" at 12434.48,4946.92 h60
  text "OTHER +/-" at 12434.46,4802.73 h60
  text "BOW & TWIST:" at 11408.23,4657.54 h60
  text "X" at 12256.46,4657.54 h60
  text "ANSI IPC-6012 TYPE 3 CLASS 2" at 12434.48,4657.54 h60
  text "OTHER +/-" at 12434.46,4510.85 h60
  text "DRILLING:" at 11333.46,4380.23 h60
  text "NC_DRILL FILES" at 13094.46,4275.04 h60
  text "REFERENCE:" at 11408.23,4271.1 h60
  text "X" at 12065.46,4271.01 h60
  text "AS SHOWN" at 12243.46,4271.1 h60
  text "X" at 12966.46,4271.1 h60
  text "OTHER" at 13392.46,4128.85 h60
  text "PTH COPPER THICKNESS:" at 11407.91,4125.32 h60
  text "X" at 12547.14,4125.32 h60
  text "20-30 um" at 12675.14,4125.32 h60
  text "BOARD FINISH:" at 11333.46,3977.73 h60
  text "SILKSCREEN:" at 11488.68,3867.6 h60
  text "X" at 12446.46,3867.6 h60
  text "TOP" at 12563.46,3867.6 h60
  text "X" at 12956.46,3867.6 h60
  text "BOTTOM" at 13074.46,3867.6 h60
  text "SILKSCREEN COLOR:" at 11488.68,3712.41 h60
  text "X" at 12445.46,3712.41 h60
  text "WHITE" at 12563.46,3712.41 h60
  text "OTHER" at 13074.46,3712.41 h60
  text "BLACK" at 13717.32,3575.85 h60
  text "GREEN" at 12694.46,3568.96 h60
  text "OTHER" at 13312.46,3568.96 h60
  text "X" at 13181,3567 h60
  text "SOLDER RESIST COLOR:" at 11488.68,3562.1 h60
  text "X" at 12576.46,3414.71 h60
  text "MATTE" at 12694.46,3414.71 h60
  text "SEMI-GLOSS" at 13312,3414.07 h60
  text "IMMERSION GOLD (ENIG)" at 12394.46,3241.94 h60
  text "ENEPIG" at 13732,3234.72 h60
  text "SURFACE FINISH:" at 11333.46,3233.72 h60
  text "X" at 12216.46,3233.72 h60
  text "IMM. TIN/SILVER OR EQUIV" at 11663,3096.4 h60
  text "OTHER" at 13094.46,3092.47 h60
  text "ARRAY/PANEL:" at 11333.46,2937.09 h60
  text "CUT AND TRIM PER M1 BOARD OUTLINE" at 12394.46,2928.87 h60
  text "N.C. ROUTE" at 12394.46,2792.9 h60
  text "X" at 13082.46,2792.9 h60
  text "V. SCORE" at 13260.46,2792.9 h60
  text "CERTIFICATION:" at 11333.46,2663.77 h60
  text "MATERIALS AND WORKMANSHIP FOR ALL PCBS" at 12058.46,2663.77 h60
  text "TO MEET OR EXCEED THE REQUIREMENTS OF:" at 12058.46,2569.71 h60
  text "X" at 11695.97,2441.08 h60
  text "ANSI IPC-A-600F CLASS ->" at 11823.96,2441.08 h60
  text "X" at 13471.97,2441.08 h60
  text "2" at 13581.96,2441.08 h60
  text "1" at 13266.96,2439.58 h60
  text "3" at 13935.96,2439.58 h60
  text "X" at 12507.97,2293.39 h60
  text "RoHS" at 12635.96,2293.39 h60
  text "OTHER" at 13280.36,2293.39 h60
  text "PER ORDER" at 13677.42,2293.39 h60
  text "ALL BOARDS MUST MEET OR EXCEED UL94-V0 REQUIREMENTS." at 11361,2139.57 h60
  text "PCB MUST BEAR THE UL94V-0 UL REGISTERED MATERIAL ID NUMBER" at 11361,2023.5 h60
  text "ADDITIONAL REQUIREMENTS:" at 11333.46,1854.08 h60
  text "MICROSECTION:" at 11408.23,1746.95 h60
  text "YES" at 12313.96,1746.95 h60
  text "REQUIRED" at 13175.46,1602.62 h60
  text "BARE BOARD ELEC. TEST:" at 11408.23,1599.76 h60
  text "NONE" at 12713.96,1599.76 h60
  text "X" at 13057.46,1599.76 h60
  text "PER ORDER" at 13767.46,1599.76 h60
  text "XX MIL VIAS REQUIRE NON-CONDUCTIVE FILL AND PLANARIZE" at 11576.38,1394.82 h59
  text "XX MIL VIAS REQUIRE CONDUCTIVE FILL AND PLANARIZE" at 11584.38,1290.84 h60
  text "OUTER XX MIL TRACES REQUIRE 50 OHM SINGLE-ENDED IMPEDANCE" at 11583.39,1127.46 h58
  text "LAYER 2 & 3 (INNER LAYERS) XX MIL WIDE, XX MIL SPACE / TRACES REQUIRE 100 OHM DIFFERENTIAL IMPEDANCE" at 11575.39,891.74 h60
  text ".Layer_Name" at 577,-858.49 h60
M11 Gerber Information:
  lines w10: -292,-930.17 6308,-930.17 ; -292,-726.83 6310,-726.83 ; -292,-523.5 -292,-1133.5 3713,-1133.5 6310,-1133.5 6310,-523.5 -291.5,-523.5 -291.5,-1133.5 1284,-1133.5 ; 2173,-1133.5 2173,-523.5 ; 3440,-726.83 3440,-523.5 ; 4280,-726.83 4280,-523.5 ; 4902,-1140 4902,-937.17
  text "ALL ARTWORK VIEWED FROM TOP SIDE" at -228.5,-655.67 h60
  text "BOARD #:" at 2248,-655.67 h60
  text ".PRJ_Number" at 2793.5,-655.67 h60
  text "REV:" at 3638,-655.67 h60
  text ".PCB_Rev" at 3929.5,-655.67 h60
  text "SVN REV:" at 4476,-655.67 h60
  text ".VersionControl_RevNumber" at 4982,-655.67 h60
  text "LAYER NAME =" at -228.5,-858.49 h60
  text "TID #:" at 2248,-859 h60
  text ".TID" at 2793.5,-859 h60
  text "PLOT NAME =" at -228.5,-1064.34 h60
  text ".plot_File_Name" at 577,-1064.34 h60
  text "GENERATED    :" at 2250,-1064.34 h60
  text ".Print_Date" at 3119.5,-1064.34 h60
  text ".Print_Time" at 3848.5,-1064.34 h60
  text "TEXAS INSTRUMENTS" at 5113,-1064.34 h60
M12 Stackup:
  drawing of 295 lines, arcs and shapes, not listed
  text "Layer" at 9821.59,7874.94 h60
  text "Name" at 10231.51,7874.94 h60
  text "Material" at 11171.25,7874.94 h60
  text "Thickness" at 12031.02,7874.94 h60
  text "Constant" at 12680.85,7874.94 h60
  text "Board Layer Stack" at 13250.71,7874.94 h60
  text "Top Overlay" at 10231.51,7754.94 h60
  text "Top Solder" at 10231.51,7634.94 h60
  text "Solder Resist" at 11171.25,7634.94 h60
  text "0.40mil" at 12031.02,7634.94 h60
  text "3.5" at 12680.85,7634.94 h60
  text "1" at 9821.59,7514.94 h60
  text "Top Layer" at 10231.51,7514.94 h60
  text "2.80mil" at 12031.02,7514.94 h60
  text "Dielectric 1" at 10231.51,7394.94 h60
  text "FR-4 High Tg" at 11171.25,7394.94 h60
  text "8.00mil" at 12031.02,7394.94 h60
  text "4.2" at 12680.85,7394.94 h60
  text "2" at 9821.59,7274.94 h60
  text "Signal Layer 1" at 10231.51,7274.94 h60
  text "1.40mil" at 12031.02,7274.94 h60
  text "Dielectric 2" at 10231.51,7154.94 h60
  text "FR-4 High Tg" at 11171.25,7154.94 h60
  text "37.20mil" at 12031.02,7154.94 h60
  text "4.2" at 12680.85,7154.94 h60
  text "3" at 9821.59,7034.94 h60
  text "Signal Layer 2" at 10231.51,7034.94 h60
  text "1.40mil" at 12031.02,7034.94 h60
  text "Dielectric 3" at 10231.51,6914.94 h60
  text "FR-4 High Tg" at 11171.25,6914.94 h60
  text "8.00mil" at 12031.02,6914.94 h60
  text "4.2" at 12680.85,6914.94 h60
  text "4" at 9821.59,6794.94 h60
  text "Bottom Layer" at 10231.51,6794.94 h60
  text "2.80mil" at 12031.02,6794.94 h60
  text "Bottom Solder" at 10231.51,6674.94 h60
  text "Solder Resist" at 11171.25,6674.94 h60
  text "0.40mil" at 12031.02,6674.94 h60
  text "3.5" at 12680.85,6674.94 h60
  text "Bottom Overlay" at 10231.51,6554.94 h60
  text ".Layer_Name" at 577,-858.49 h60
M13 Component Bodies Top:
  text ".Layer_Name" at 577,-858.49 h60
M14 Component Bodies Bottom:
  text ".Layer_Name" at 577,-858.49 h60
M15 Courtyards Top:
  text ".Layer_Name" at 577,-858.49 h60
M16 Courtyards Bottom:
  text ".Layer_Name" at 577,-858.49 h60
Drill Drawing:
  circle w10: c5363.72,3041.64 r16.58
  circle w10: c5363.72,3041.64 r27.63
  circle w10: c5363.72,2544.36 r27.63
  lines w10: 5336.09,2143.78 5363.72,2157.59 5391.34,2143.78 5377.53,2171.4 5391.34,2199.03 5363.72,2185.22 5336.09,2199.03 5349.9,2171.4 5336.09,2143.78 ; 5336.09,2268.1 5391.34,2268.1 5391.34,2323.35 5336.09,2323.35 5336.09,2268.1 ; 5336.09,2406.23 5349.9,2406.23 5363.72,2392.42 5377.53,2406.23 5391.34,2406.23 5377.53,2420.04 5391.34,2433.86 5377.53,2433.86 5363.72,2447.67 5349.9,2433.86 5336.09,2433.86 5349.9,2420.04 5336.09,2406.23 ; 5336.09,2641.06 5336.09,2654.87 5349.9,2668.68 5336.09,2682.5 5336.09,2696.31 5349.9,2696.31 5363.72,2682.5 5377.53,2696.31 5391.34,2696.31 5391.34,2682.5 5377.53,2668.68 5391.34,2654.87 5391.34,2641.06 5377.53,2641.06 5363.72,2654.87 5349.9,2641.06 5336.09,2641.06 ; 5336.09,2820.63 5391.34,2820.63 5363.72,2765.38 5336.09,2820.63 ; 5336.09,2889.7 5391.34,2889.7 5391.34,2944.95 5336.09,2944.95 5336.09,2889.7 ; 5336.09,3165.96 5363.72,3138.34 5391.34,3165.96 5363.72,3193.59 5336.09,3165.96 ; 5336.09,3276.47 5349.9,3276.47 5349.9,3262.66 5377.53,3262.66 5377.53,3276.47 5391.34,3276.47 5391.34,3304.1 5377.53,3304.1 5377.53,3317.91 5349.9,3317.91 5349.9,3304.1 5336.09,3304.1 5336.09,3276.47 ; 5347.14,2900.75 5380.29,2900.75 5380.29,2933.9 5347.14,2933.9 5347.14,2900.75
  lines w12: 5286,2106.48 8517.49,2106.48 ; 5286,3349.68 8517.49,3349.68 ; 5623.86,1982.16 5623.86,3474 ; 5955.86,1982.16 5955.86,3474 ; 6592.43,1982.16 6592.43,3474 ; 6851.57,1982.16 6851.57,3474 ; 7226.72,1982.16 7226.72,3474 ; 7951.05,1982.16 7951.05,3474 ; 5286,1982.16 8517.49,1982.16 8517.49,3474 5286,3474 5286,1982.16
  text "Symbol" at 5360.59,3386.98 h72
  text "Quantity" at 5661.16,3386.98 h72
  text "Finished Hole Size" at 5993.16,3386.98 h72
  text "Plated" at 6629.72,3386.98 h72
  text "Hole Type" at 6888.86,3386.98 h72
  text "Drill Layer Pair" at 7264.02,3386.98 h72
  text "Hole Tolerance" at 7988.35,3386.98 h72
  text "7" at 5661.16,3262.66 h60
  text "7.87mil (0.200mm)" at 5993.16,3262.66 h60
  text "PTH" at 6629.72,3262.66 h60
  text "Round" at 6888.86,3262.66 h60
  text "Top Layer - Bottom Layer" at 7264.02,3262.66 h60
  text "179" at 5661.16,3138.34 h60
  text "8.00mil (0.203mm)" at 5993.16,3138.34 h60
  text "PTH" at 6629.72,3138.34 h60
  text "Round" at 6888.86,3138.34 h60
  text "Top Layer - Bottom Layer" at 7264.02,3138.34 h60
  text "262" at 5661.16,3014.02 h60
  text "10.00mil (0.254mm)" at 5993.16,3014.02 h60
  text "PTH" at 6629.72,3014.02 h60
  text "Round" at 6888.86,3014.02 h60
  text "Top Layer - Bottom Layer" at 7264.02,3014.02 h60
  text "2" at 5661.16,2889.7 h60
  text "16.00mil (0.406mm)" at 5993.16,2889.7 h60
  text "PTH" at 6629.72,2889.7 h60
  text "Round" at 6888.86,2889.7 h60
  text "Top Layer - Bottom Layer" at 7264.02,2889.7 h60
  text "4" at 5661.16,2765.38 h60
  text "35.43mil (0.900mm)" at 5993.16,2765.38 h60
  text "PTH" at 6629.72,2765.38 h60
  text "Round" at 6888.86,2765.38 h60
  text "Top Layer - Bottom Layer" at 7264.02,2765.38 h60
  text "6" at 5661.16,2641.06 h60
  text "40.00mil (1.016mm)" at 5993.16,2641.06 h60
  text "PTH" at 6629.72,2641.06 h60
  text "Round" at 6888.86,2641.06 h60
  text "Top Layer - Bottom Layer" at 7264.02,2641.06 h60
  text "15" at 5661.16,2516.74 h60
  text "40.16mil (1.020mm)" at 5993.16,2516.74 h60
  text "PTH" at 6629.72,2516.74 h60
  text "Round" at 6888.86,2516.74 h60
  text "Top Layer - Bottom Layer" at 7264.02,2516.74 h60
  text "8" at 5661.16,2392.42 h60
  text "62.99mil (1.600mm)" at 5993.16,2392.42 h60
  text "PTH" at 6629.72,2392.42 h60
  text "Round" at 6888.86,2392.42 h60
  text "Top Layer - Bottom Layer" at 7264.02,2392.42 h60
  text "13" at 5661.16,2268.1 h60
  text "63.00mil (1.600mm)" at 5993.16,2268.1 h60
  text "PTH" at 6629.72,2268.1 h60
  text "Round" at 6888.86,2268.1 h60
  text "Top Layer - Bottom Layer" at 7264.02,2268.1 h60
  text "4" at 5661.16,2143.78 h60
  text "125.98mil (3.200mm)" at 5993.16,2143.78 h60
  text "PTH" at 6629.72,2143.78 h60
  text "Round" at 6888.86,2143.78 h60
  text "Top Layer - Bottom Layer" at 7264.02,2143.78 h60
  text "500 Total" at 5661.16,2019.46 h60
  text ".Layer_Name" at 577,-858.49 h60
M17 Embedded Cavity:
  text ".Layer_Name" at 577,-858.49 h60
M18 Embedded Assembly:
  text ".Layer_Name" at 577,-858.49 h60
M19 Embedded Keepout:
  text ".Layer_Name" at 577,-858.49 h60

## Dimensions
0,-400 to 1000,-400 on M2 Board Dimensions
0,0 to 0,2763 on M2 Board Dimensions
0,0 to 4000,0 on M2 Board Dimensions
